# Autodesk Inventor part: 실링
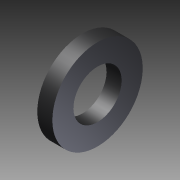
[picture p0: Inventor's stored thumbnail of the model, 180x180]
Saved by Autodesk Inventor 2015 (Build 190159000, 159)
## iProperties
Created: 2026-04
Part Number: 실링
Material: 일반
Document SubType Name: Modeling
Designer: User
Density: 1 g/cm^3
Appearance: 기본값
Author: User
Author: jhkim
Creation Date: 2026-03-26
Sending System: Autodesk Inventor 2026
Preprocessor: ST-DEVELOPER v20.1
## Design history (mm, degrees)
node "실링1"
node "솔리드1"
node "기준1"
